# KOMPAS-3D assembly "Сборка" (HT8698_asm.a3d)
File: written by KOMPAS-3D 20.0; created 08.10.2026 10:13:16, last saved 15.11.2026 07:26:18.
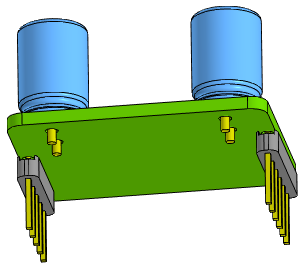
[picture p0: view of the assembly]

Document properties: Полное имя файла: D:\myProjects\Progect_esp32\box_compas\усилитель\HT8698_asm.a3d

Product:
- Part/product: Сборка
    Масса: 0.0184861
  - Component [detail]: Деталь  | Масса: 0.000635679; source file: ..\разъемы\pls_5.m3d
  - Component [detail]: Деталь  | Масса: 0.000766031; source file: ..\разъемы\pls_6.m3d
  - Component [detail]: Деталь  | Масса: 0.00813166; source file: HT8698.m3d
  - Component [detail]: Деталь  | qty 2  | Масса: 0.00447634; source file: ..\прочее\1000mkf 8x11.5 p3.5 (JRB1A102M03500800115000B).m3d

Referenced files in D:\myProjects\Progect_esp32\box_compas\усилитель\: HT8698.m3d
Referenced files in D:\myProjects\Progect_esp32\box_compas\разъемы\: pls_6.m3d, pls_5.m3d
Referenced files in D:\myProjects\Progect_esp32\box_compas\прочее\: 1000mkf 8x11.5 p3.5 (JRB1A102M03500800115000B).m3d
